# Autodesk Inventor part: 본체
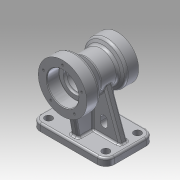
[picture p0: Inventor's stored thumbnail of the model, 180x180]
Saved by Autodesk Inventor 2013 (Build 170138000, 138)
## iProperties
Created: 2015-08
Part Number: 본체
Material: 알루미늄 6061
Document SubType Name: Modeling
Designer: dgall
Mass: 1062.37 g
Surface Area: 750.557 cm^2
Volume: 392.018 cm^3
Density: 2.71 g/cm^3
Author: dgall
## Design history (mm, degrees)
sketch "스케치1"
  geometry: L1 (0, 0)-(122, 0); L2 (122, 0)-(122, 80); L3 (122, 80)-(0, 80); L4 (0, 80)-(0, 0)
  constraints: 8 end point, 2 parallel, 1 horizontal, 1 perpendicular
  dimensions: "d0" = 122 distance of L1.start L1.end; "d1" = 80 distance of L3.end L1.start
extrude "돌출1" new body sketch "스케치1" distance "d2" = 12; taper "d3" = 0 deg
node "작업 평면1"
sketch "스케치2"
  geometry: L1 (80, 0)-(0, 0) reference; L2 (0, 0)-(0, 12) reference; L3 (80, 12)-(0, 12) reference; L4 (80, 0)-(80, 12) reference; L5 (-10, 90)-(80, 90); L6 (-10, 130)-(10, 130); L7 (10, 130)-(26.685, 116); L8 (26.685, 116)-(54.804, 116); L9 (54.804, 116)-(60, 125); L10 (60, 125)-(80, 125); L11 (80, 125)-(80, 90); L12 (-10, 130)-(-10, 90); L13 (-10, 116)-(10, 116); L14 (10, 116)-(10, 109); L15 (10, 109)-(13, 109); L16 (13, 109)-(13, 106); L17 (13, 106)-(63, 106); L18 (63, 106)-(63, 110); L19 (63, 110)-(80, 110); 1 further point
  constraints: 30 end point, 8 parallel, 5 perpendicular, 2 point on line
  dimensions: "d4" = 90 distance of L5.start L5.end; "d7" = 90 distance of L1.start L5.end; "d9" = 80 diameter of L6 L5; "d10" = 70 diameter of L10 L5; "d12" = 60 deg angle of L8 L9; "d13" = 52 diameter of L8 L5; "d14" = 40 deg angle of L8 L7; "d15" = 20 distance of L6.start L6.end; "d16" = 20 distance of L9.end L10.end; "d17" = 52 diameter of L13 L5; "d18" = 38 diameter of L15 L5; "d19" = 32 diameter of L17 L5; "d20" = 40 diameter of L19 L5; "d21" = 20 distance between parallel lines of L14 L12; "d22" = 3 distance between parallel lines of L16 L14; "d23" = 17 distance between parallel lines of L11 L18; "d25" = 10 distance between parallel lines of L12 L2
revolve "회전1" sketch "스케치2" stored, may be unused: angle "d24" = 90 deg
node "작업 평면2"
sketch "스케치3"
  geometry: L1 (-122, 0)-(0, 0) reference; L2 (0, 0)-(0, 12) reference; L3 (-122, 12)-(0, 12) reference; L4 (-122, 0)-(-122, 12) reference; L5 (-10, 12)-(-35.909, 83.185); L6 (-112, 12)-(-86.091, 83.185); C1 r 20 at (-61, 90) reference; C2 r 35 at (-61, 90) reference; A1 r 26 centre (-61, 90) between (-86.091, 83.185) and (-35.909, 83.185) reference; 1 further point
  constraints: 4 end point, 2 point on circle, 2 point on line
  dimensions: "d29" = 70 deg angle of L3 L5; "d30" = 10 distance from line of L2 L5.start; "d31" = 70 deg angle of L3 L6; "d32" = 10 distance from line of L4 L6.start
extrude "돌출2" join sketch "스케치3" stored distance "d33" = 12; taper "d34" = 0 deg
node "작업 평면3"
sketch "스케치4"
  geometry: L1 (0, 0)-(80, 0) reference; L2 (80, 0)-(80, 12) reference; L3 (0, 12)-(80, 12) reference; L4 (0, 0)-(0, 12) reference; L5 (10, 50)-(10, 130) reference; L6 (-10, 50)-(-10, 130) reference; L7 (26.685, 64)-(26.685, 116) reference; L8 (10, 50)-(10, 130) reference; L9 (80, 55)-(80, 125) reference; L10 (60, 55)-(60, 125) reference; L11 (60, 55)-(60, 125) reference; L12 (54.804, 64)-(54.804, 116) reference; L13 (34, 83.185)-(34, 83.185) reference; L14 (34, 83.185)-(46, 83.185) reference; L15 (46, 83.185)-(46, 83.185) reference; L16 (46, 83.185)-(34, 83.185) reference; L17 (54.804, 64)-(54.804, 116) reference; L18 (26.685, 64)-(26.685, 116) reference; L19 (10, 12)-(3.177, 50.697); L20 (70, 12)-(70, 55); L21 (60, 55)-(80, 55) reference; L22 (-10, 50)-(10, 50) reference; L23 (10, 50)-(26.685, 64) reference; L24 (26.685, 64)-(54.804, 64) reference; L25 (54.804, 64)-(60, 55) reference; L26 (70, 12)-(10, 12); 1 further point
  constraints: 6 end point, 2 point on line, 1 collinear, 1 parallel
  dimensions: "d35" = 10 distance from line of L19.start L4; "d36" = 80 deg angle of L3 L19; "d37" = 10 distance of L2.end L20.start
feature "리브1" sketch "스케치4" dims "d38" = 1, "d39" = 12, "d40" = 0, "d41" = 0, "d42" = 1, "d43" = 1
fillet "모깎기1" dims "d44" = 14
sketch "스케치5"
  geometry: C1 r 6 at (14, 66); A1 r 14 centre (14, 66) between (14, 80) and (0, 66) reference; 1 further point
  constraints: 1 centre point, 1 coincident
  dimensions: "d45" = 12 diameter of C1
extrude "돌출3" cut sketch "스케치5" stored distance "d47" = 12; taper "d48" = 0 deg
sketch "스케치6"
  geometry: L1 (55, 12)-(10, 12) reference; L2 (31, 36)-(31, 30); L3 (43, 30)-(43, 36); L4 (55, 50.453)-(55, 12) reference; L5 (67, 12)-(55, 12) reference; L6 (67, 12)-(67, 50.453) reference; L7 (61, 12)-(61, 50); A1 r 6 centre (37, 30) between (31, 30) and (43, 30); A2 r 6 centre (37, 36) between (43, 36) and (31, 36); A3 r 40 centre (61, 90) between (55, 50.453) and (67, 50.453) reference; 1 further point
  constraints: 6 end point, 5 point on circle, 4 tangent, 2 centre point, 1 midpoint, 1 parallel, 1 perpendicular
  dimensions: "d55" = 24 horizontal distance of L7.start A1.centre; "d57" = 18 distance from line of L1 A1.centre; "d58" = 12 distance between parallel lines of L2 L3; "d59" = 18 dimension on A1 A2
extrude "돌출4" cut sketch "스케치6" stored distance "d60" = 12; taper "d61" = 0 deg
sketch "스케치7"
  geometry: C1 r 26 at (0, 0) reference; 2 further points
  dimensions: "d65" = 33 distance of C1.centre point (0, 33)
hole "구멍1" sketch "스케치7" at (0, 33) diameter "d66" = 3.459; stored, may be unused: countersink angle "d70" = 90 deg, drill point angle "d72" = 118 deg; dims "d67" = 10, "d68" = 4, "d69" = 2, "d71" = 13
sketch "스케치8"
  geometry: C1 r 20 at (0, 0) reference; 2 further points
  dimensions: "d76" = 27 distance of C1.centre point (0, -27)
hole "구멍2" sketch "스케치8" at (0, -27) diameter "d77" = 3.459; stored, may be unused: countersink angle "d81" = 90 deg, drill point angle "d83" = 118 deg; dims "d78" = 10, "d79" = 4, "d80" = 2, "d82" = 13
fillet "모깎기2" dims "d87" = 5
node "작업 평면4"
fillet "모깎기3" dims "d88" = 0.3
fillet "모깎기4" dims "d89" = 0.3
chamfer "모따기1" distance "d90" = 1; stored, may be unused: second distance "d91" = 2, angle "d92" = 45 deg
fillet "모깎기5" dims "d93" = 3
fillet "모깎기6" dims "d94" = 3
fillet "모깎기7" dims "d95" = 3
fillet "모깎기8" dims "d96" = 3
sketch "스케치9"
  geometry: L1 (-41.969, -5.284)-(7.806, -5.284); L2 (7.806, -5.284)-(7.806, -12.489); L3 (7.806, -12.489)-(-41.969, -12.489); L4 (-41.969, -12.489)-(-41.969, -5.284); L5 (-17.081, -12.489)-(-17.081, -5.284); L6 (7.806, -8.887)-(-41.969, -8.887); L7 (-17.081, -8.887)-(-16.751, -8.617); L8 (-41.081, -48.887)-(-41.081, 3.113) reference; L9 (-0.963, 7.113)-(-38.081, 7.113) reference; 1 further point
  constraints: 6 end point, 5 midpoint, 2 other
  dimensions: "d97" = 24 distance from line of L8 L7.start; "d98" = 16 distance from line of L7.start L9
feature "엠보싱1" sketch "스케치9" dims "d0" = 122, "d1" = 80, "d99" = 0.5, "d100" = 0
node "솔리드1"
pattern_linear "직사각형 패턴1" dims "d51" = 94, "d54" = 52
pattern_linear "직사각형 패턴2" dims "d64" = 48
pattern_circular "원형 패턴1" dims angle "d74" = 360 deg
pattern_circular "원형 패턴2" dims angle "d85" = 360 deg
node "투영된 루프1"
node "투영된 루프2"
node "투영된 루프3"
node "투영된 루프4"
node "투영된 루프5"
node "투영된 루프6"
node "투영된 루프7"
node "투영된 루프8"
node "투영된 루프9"
node "투영된 루프10"
